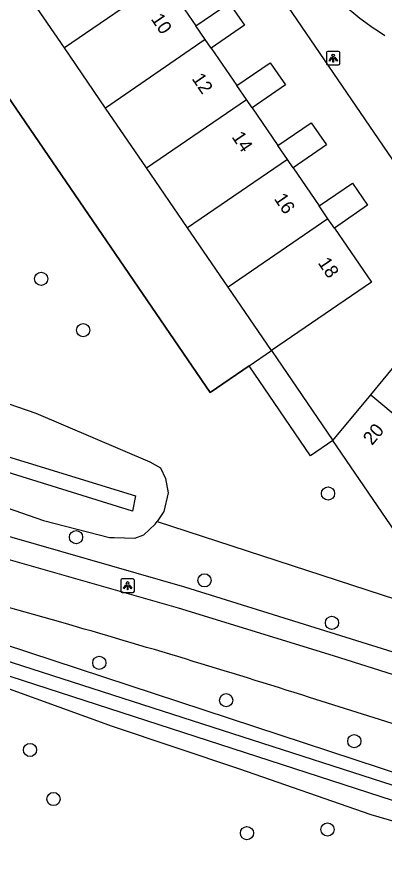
# Model space of a CAD drawing. Extents: x 155275 to 156263, y 382654 to 383635.
# Drawn here: x 155535.7 to 155562.9, y 382818.2 to 382882.1 of the extents above; entities that cross this region are included whole.
import ezdxf

# ---------------------------------------------------------------- set-up
doc = ezdxf.new("R2010")
doc.units = 0
for name, color, linetype in [('IMGEO_Berm_groen', 7, 'Continuous'), ('IMGEO_Boom', 7, 'Continuous'), ('IMGEO_Fietspad_gesloten', 7, 'Continuous'), ('IMGEO_Groenvoorziening', 7, 'Continuous'), ('IMGEO_Lichtpunt', 7, 'Continuous'), ('IMGEO_Muur', 7, 'Continuous'), ('IMGEO_Pand', 7, 'Continuous'), ('IMGEO_Pand_nummerreeks', 7, 'Continuous'), ('IMGEO_Voetpad_op_trap', 7, 'Continuous'), ('IMGEO_Voetpad_open', 7, 'Continuous'), ('IMGEO_Waterloop', 7, 'Continuous')]:
    doc.layers.add(name, color=color, linetype=linetype)

msp = doc.modelspace()

# ---------------------------------------------------------------- linework, layer by layer
at = {"layer": 'IMGEO_Berm_groen'}
for points in [[(155509.683, 382857.207), (155509.505, 382856.569), (155509.49, 382855.157), (155509.834, 382854.007), (155510.471, 382853.211), (155512.141, 382852.495), (155528.278, 382847.932), (155537.612, 382844.689), (155542.498, 382843.434), (155542.841, 382843.423), (155544.372, 382843.376), (155545.058, 382843.634), (155545.886, 382844.407), (155546.035, 382844.625)], [(155546.035, 382844.625), (155577.143, 382834.463), (155577.778, 382834.255)], [(155509.582, 382844.192), (155511.113, 382843.854), (155513.914, 382843.177), (155517.021, 382842.147), (155533.935, 382835.744), (155534.617, 382835.527), (155592.371, 382816.512), (155598.661, 382815.045), (155599.059, 382814.706), (155599.035, 382814.318), (155599.022, 382814.105), (155598.741, 382813.293), (155598.343, 382812.426), (155597.963, 382812.03), (155597.867, 382812.01)], [(155597.867, 382812.01), (155597.201, 382811.872), (155596.451, 382811.962), (155594.7, 382812.708), (155573.042, 382819.602), (155561.916, 382822.836), (155552.105, 382826.241), (155542.735, 382829.389), (155531.099, 382833.594), (155523.881, 382835.906), (155514.687, 382838.613), (155507.825, 382840.77)]]:
    msp.add_lwpolyline(points, dxfattribs=at)
at = {"layer": 'IMGEO_Boom'}
for centre in [(155537.426, 382862.632), (155540.55, 382858.819), (155558.717, 382846.697), (155540.022, 382843.446), (155549.55, 382840.244), (155559.009, 382837.085), (155541.747, 382834.118), (155551.156, 382831.341), (155560.664, 382828.3), (155536.604, 382827.651), (155538.347, 382824.007), (155552.703, 382821.476), (155558.682, 382821.742)]:
    msp.add_circle(centre, 0.489, dxfattribs=at)
at = {"layer": 'IMGEO_Fietspad_gesloten'}
for points in [[(155538.9, 382837.129), (155518.652, 382842.797), (155510.232, 382845.458)], [(155533.04, 382842.358), (155547.598, 382838.191), (155559.094, 382834.658), (155572.372, 382830.457)], [(155900.914, 382719.832), (155759.673, 382765.919), (155663.46, 382797.119), (155571.34, 382827.145), (155557.345, 382831.556)]]:
    msp.add_lwpolyline(points, dxfattribs=at)
msp.add_arc((155339.124, 382142.619), 722.672, 72.424396, 73.952113, dxfattribs=at)
at = {"layer": 'IMGEO_Groenvoorziening'}
for points in [[(155552.869, 382856.181), (155549.963, 382854.195), (155523.867, 382892.372)], [(155509.683, 382857.207), (155509.686, 382857.22), (155509.803, 382857.492), (155510.464, 382858.305), (155511.221, 382858.76), (155512.363, 382859.081), (155515.757, 382859.159), (155522.027, 382857.764), (155528.214, 382855.694), (155537.025, 382852.647), (155545.495, 382849.034), (155546.28, 382848.593), (155546.666, 382847.799), (155546.852, 382846.735), (155546.534, 382845.357), (155546.035, 382844.625)]]:
    msp.add_lwpolyline(points, dxfattribs=at)
msp.add_arc((155574.849, 382899.783), 22.494, 215.00387, 237.99673, dxfattribs=at)
at = {"layer": 'IMGEO_Lichtpunt'}
for p, q in [((155559.506, 382879.522), (155558.698, 382879.522)), ((155559.506, 382879.522), (155558.698, 382879.522)), ((155558.604, 382879.427), (155558.604, 382878.62)), ((155558.604, 382879.427), (155558.604, 382878.62)), ((155559.6, 382878.62), (155559.6, 382879.427)), ((155559.6, 382878.62), (155559.6, 382879.427)), ((155558.698, 382878.526), (155559.506, 382878.526)), ((155558.698, 382878.526), (155559.506, 382878.526)), ((155543.35, 382840.25), (155543.35, 382839.443)), ((155543.35, 382840.25), (155543.35, 382839.443)), ((155544.252, 382840.345), (155543.444, 382840.345)), ((155544.252, 382840.345), (155543.444, 382840.345)), ((155544.346, 382839.443), (155544.346, 382840.25)), ((155544.346, 382839.443), (155544.346, 382840.25)), ((155543.444, 382839.349), (155544.252, 382839.349)), ((155543.444, 382839.349), (155544.252, 382839.349))]:
    msp.add_line(p, q, dxfattribs=at)
for points in [[(155558.978, 382879.091), (155559.017, 382879.063), (155558.829, 382878.801), (155558.791, 382878.828), (155558.978, 382879.091)], [(155559.08, 382879.043), (155559.127, 382879.043), (155559.127, 382878.721), (155559.08, 382878.721), (155559.08, 382879.043)], [(155559.19, 382879.063), (155559.228, 382879.09), (155559.415, 382878.828), (155559.376, 382878.8), (155559.19, 382879.063)], [(155543.724, 382839.914), (155543.763, 382839.886), (155543.575, 382839.624), (155543.537, 382839.651), (155543.724, 382839.914)], [(155543.826, 382839.866), (155543.873, 382839.866), (155543.873, 382839.544), (155543.826, 382839.544), (155543.826, 382839.866)], [(155543.936, 382839.886), (155543.974, 382839.913), (155544.161, 382839.651), (155544.122, 382839.623), (155543.936, 382839.886)]]:
    msp.add_lwpolyline(points, dxfattribs=at)
for centre in [(155559.103, 382879.225), (155543.849, 382840.048)]:
    msp.add_circle(centre, 0.0994, dxfattribs=at)
for centre, start, end in [((155558.698, 382879.427), 90, 180), ((155558.698, 382879.427), 90, 180), ((155559.506, 382879.427), 0, 90), ((155559.506, 382879.427), 0, 90), ((155558.698, 382878.62), 180, 270), ((155558.698, 382878.62), 180, 270), ((155559.506, 382878.62), 270, 0), ((155559.506, 382878.62), 270, 360), ((155543.444, 382840.25), 90, 180), ((155543.444, 382840.25), 90, 180), ((155544.252, 382840.25), 0, 90), ((155544.252, 382840.25), 0, 90), ((155543.444, 382839.443), 180, 270), ((155543.444, 382839.443), 180, 270), ((155544.252, 382839.443), 270, 0), ((155544.252, 382839.443), 270, 360)]:
    msp.add_arc(centre, 0.0946, start, end, dxfattribs=at)
at = {"layer": 'IMGEO_Muur'}
msp.add_lwpolyline([(155527.511, 382896.822), (155523.867, 382892.372), (155549.963, 382854.195), (155552.869, 382856.181), (155554.52, 382857.31)], dxfattribs=at)
at = {"layer": 'IMGEO_Pand'}
for points in [[(155546.555, 382884.871), (155539.154, 382879.789)], [(155539.154, 382879.789), (155536.09, 382884.272)], [(155547, 382884.22), (155548.917, 382881.418)], [(155548.917, 382881.418), (155551.385, 382883.107), (155552.522, 382881.467), (155550.044, 382879.771)], [(155549.613, 382880.401), (155548.917, 382881.418)], [(155549.613, 382880.401), (155542.211, 382875.317)], [(155550.044, 382879.771), (155549.613, 382880.401)], [(155542.211, 382875.317), (155539.154, 382879.789)], [(155550.044, 382879.771), (155551.953, 382876.98)], [(155551.953, 382876.98), (155554.419, 382878.667), (155555.556, 382877.027), (155553.08, 382875.333)], [(155552.657, 382875.951), (155551.953, 382876.98)], [(155545.253, 382870.867), (155552.657, 382875.951)], [(155553.08, 382875.333), (155552.657, 382875.951)], [(155545.253, 382870.867), (155542.211, 382875.317)], [(155553.08, 382875.333), (155554.996, 382872.531)], [(155554.996, 382872.531), (155557.458, 382874.215), (155558.595, 382872.575), (155556.123, 382870.884)], [(155555.701, 382871.501), (155554.996, 382872.531)], [(155555.701, 382871.501), (155548.296, 382866.416)], [(155556.123, 382870.884), (155555.701, 382871.501)], [(155548.296, 382866.416), (155545.253, 382870.867)], [(155556.123, 382870.884), (155558.059, 382868.054)], [(155558.059, 382868.054), (155560.521, 382869.738), (155561.657, 382868.097), (155559.186, 382866.407)], [(155558.715, 382867.096), (155558.059, 382868.054)], [(155558.715, 382867.096), (155551.308, 382862.009)], [(155559.186, 382866.407), (155558.715, 382867.096)], [(155551.308, 382862.009), (155548.296, 382866.416)], [(155559.186, 382866.407), (155561.938, 382862.384), (155554.52, 382857.31)], [(155554.52, 382857.31), (155551.308, 382862.009)], [(155561.883, 382854.009), (155565.343, 382858.191)], [(155559.081, 382850.622), (155561.883, 382854.009)], [(155561.883, 382854.009), (155568.79, 382848.247)], [(155564.357, 382842.893), (155559.081, 382850.622)]]:
    msp.add_lwpolyline(points, dxfattribs=at)
at = {"layer": 'IMGEO_Voetpad_op_trap'}
for points in [[(155552.869, 382856.181), (155554.52, 382857.31)], [(155559.081, 382850.622), (155557.429, 382849.494), (155552.869, 382856.181)]]:
    msp.add_lwpolyline(points, dxfattribs=at)
at = {"layer": 'IMGEO_Voetpad_open'}
for points in [[(155574.495, 382882.059), (155576.86, 382879.581), (155566.513, 382867.099), (155554.075, 382885.324), (155556.424, 382886.88)], [(155554.52, 382857.31), (155559.081, 382850.622)], [(155572.372, 382830.457), (155572.828, 382832.003), (155548.087, 382839.742), (155533.441, 382843.944)]]:
    msp.add_lwpolyline(points, dxfattribs=at)
at = {"layer": 'IMGEO_Waterloop'}
for points in [[(155512.546, 382856.315), (155544.443, 382846.526), (155544.197, 382845.39), (155512.241, 382855.332), (155512.546, 382856.315)], [(155507.932, 382842.691), (155507.698, 382842.012), (155597.339, 382812.933), (155597.715, 382813.99), (155518.165, 382839.635), (155516.75, 382840.029), (155507.932, 382842.691)]]:
    msp.add_lwpolyline(points, dxfattribs=at)

# ---------------------------------------------------------------- texts
at = {"layer": 'IMGEO_Pand_nummerreeks'}
for s, rotation, p in [('10', 304.18245, (155545.54, 382881.931)), ('12', 304.17099, (155548.575, 382877.496)), ('14', 304.16526, (155551.534, 382873.169)), ('16', 304.17672, (155554.675, 382868.578)), ('18', 304.17672, (155557.931, 382863.819)), ('20', 50.19683, (155561.984, 382850.214))]:
    msp.add_text(s, height=1, rotation=rotation, dxfattribs=at).set_placement(p)

doc.saveas('drawing.dxf')
